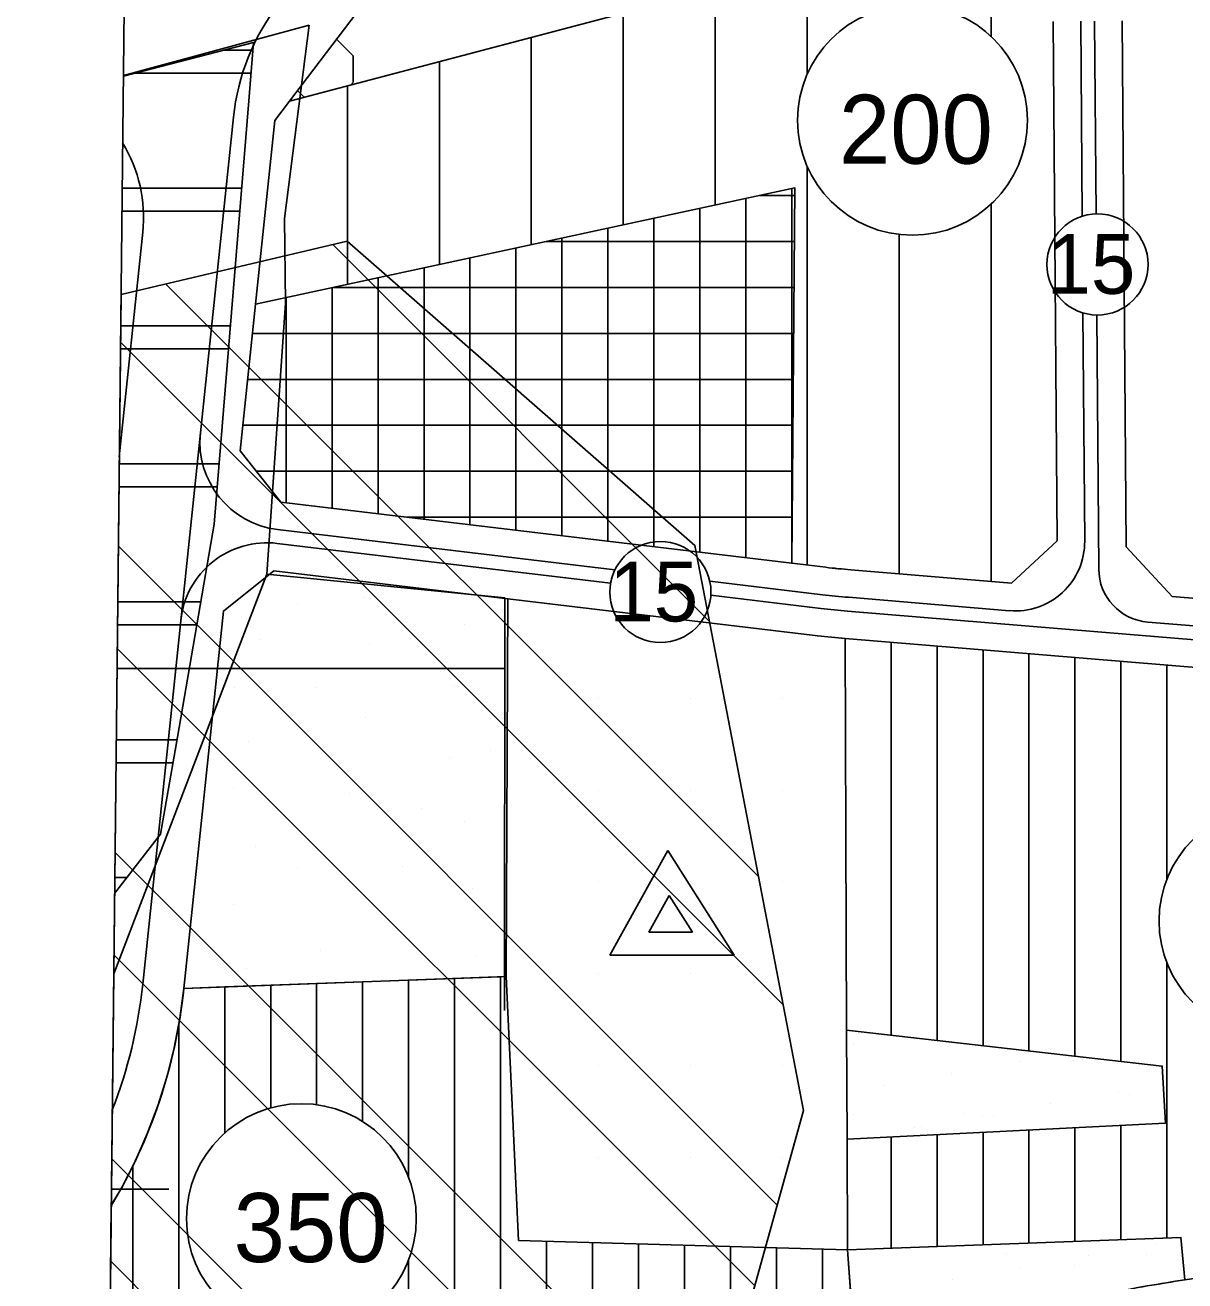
# Model space of a CAD drawing. Extents: x 419109 to 421295, y 4452223 to 4457798.
# Drawn here: x 419108.7 to 419361, y 4453980 to 4454253.2 of the extents above; entities that cross this region are included whole.
import ezdxf

# ---------------------------------------------------------------- set-up
doc = ezdxf.new("R2010")
doc.units = 0
for name, color, linetype in [('ADA', 7, 'Continuous'), ('ADAKENARI', 7, 'Continuous'), ('Default', 7, 'Continuous'), ('KALDIRIM', 7, 'Continuous'), ('KD_DAIRE', 7, 'Continuous'), ('KD_YGEN', 7, 'Continuous'), ('LJ_SEMBOL', 7, 'Continuous'), ('PAFTALAMA', 7, 'Continuous'), ('PL_AYA_AGACLANDIRIL', 7, 'Continuous'), ('PL_AYA_PARK_DINLENME', 7, 'Continuous'), ('PL_K_TALI_IS_MRK', 7, 'Continuous'), ('PL_KON_MEV_200', 7, 'Continuous'), ('PL_KON_MEV_350', 7, 'Continuous'), ('PL_SAY_ORTAOGRETIM', 7, 'Continuous'), ('rezerv yapı alan', 7, 'Continuous'), ('SIT_1_DER_DOGAL', 7, 'Continuous'), ('SIT_TR_DOGALSIT', 7, 'Continuous'), ('SM_DAIRE', 7, 'Continuous'), ('SM_TAKS', 7, 'Continuous'), ('SN_JE_SIVILASMA', 7, 'Continuous'), ('SN_TR_SIVILASMA', 7, 'Continuous'), ('TR_AGACALANI', 7, 'Continuous'), ('TR_AZYOGUNKONUT', 7, 'Continuous'), ('TR_ORTAEGITIM', 7, 'Continuous'), ('TR_ORTAYOGUNKONUT', 7, 'Continuous'), ('TR_PARKALANI', 7, 'Continuous'), ('TR_TALIISMERK', 7, 'Continuous')]:
    doc.layers.add(name, color=color, linetype=linetype)

# ---------------------------------------------------------------- blocks, each defined once
blk = doc.blocks.new('POINT_DISPLAY')
at = {"layer": 'Default'}
blk.add_line((0, 0), (0, 0), dxfattribs=at)

msp = doc.modelspace()

# ---------------------------------------------------------------- linework, layer by layer
at = {"layer": 'ADA'}
for p, q in [((419166.21, 4454236.66), (419331.42, 4454280.21)), ((419158.82, 4454192.46), (419276.17, 4454217.78)), ((419276.17, 4454217.78), (419275.48, 4454136.13)), ((419213.73, 4454128.4), (419213.38, 4454046.22)), ((419287.07, 4454119.75), (419287.4, 4454034.53)), ((419213.38, 4454046.22), (419143.26, 4454043.64)), ((419216.07, 4453988.81), (419213.38, 4454046.22)), ((419287.4, 4454034.53), (419287.49, 4454010.85)), ((419356.07, 4454026.75), (419287.4, 4454034.53)), ((419356.74, 4454014.33), (419356.07, 4454026.75)), ((419287.49, 4454010.85), (419356.74, 4454014.33)), ((419287.49, 4454010.85), (419287.58, 4453986.8)), ((419287.58, 4453986.8), (419216.07, 4453988.81)), ((419360.1, 4453989.49), (419287.58, 4453986.8)), ((419360.98, 4453980.26), (419360.1, 4453989.49)), ((419287.58, 4453986.8), (419289.1, 4453966.24))]:
    msp.add_line(p, q, dxfattribs=at)
at = {"layer": 'ADAKENARI'}
for p, q in [((419166.21, 4454236.66), (419188.8, 4454266.34)), ((419332.34, 4454253.99), (419333.19, 4454140.97)), ((419348.2, 4454139.73), (419347.34, 4454254.1)), ((419163, 4454232.45), (419166.21, 4454236.66)), ((419158.82, 4454192.46), (419163, 4454232.45)), ((419155.48, 4454160.55), (419158.82, 4454192.46)), ((419164.37, 4454149.41), (419155.48, 4454160.55)), ((419275.48, 4454136.13), (419164.37, 4454149.41)), ((419333.19, 4454140.97), (419323.3, 4454131.8)), ((419358.24, 4454128.9), (419348.2, 4454139.73)), ((419282.89, 4454135.24), (419275.48, 4454136.13)), ((419151.84, 4454125.73), (419162.81, 4454134.49)), ((419162.81, 4454134.49), (419213.73, 4454128.4)), ((419323.3, 4454131.8), (419288.31, 4454134.7)), ((419213.73, 4454128.4), (419281.11, 4454120.35)), ((419364.39, 4454128.39), (419358.24, 4454128.9)), ((419143.26, 4454043.64), (419151.84, 4454125.73)), ((419287.07, 4454119.75), (419365.19, 4454113.28))]:
    msp.add_line(p, q, dxfattribs=at)
for centre, radius, start, end in [((419300.69, 4454284.18), 150, 263.1826, 265.2652), ((419300.69, 4454284.18), 165, 263.1826, 265.2652), ((419028.88, 4454055.6), 115, 329.0052, 354.0304), ((419411.58, 4453644.04), 340, 98.5592, 101.3544)]:
    msp.add_arc(centre, radius, start, end, dxfattribs=at)
at = {"layer": 'KALDIRIM'}
for p, q in [((419338.34, 4454254.04), (419338.66, 4454211.61)), ((419341.34, 4454254.06), (419341.65, 4454212.12)), ((419154.03, 4454233.14), (419146.85, 4454164.49)), ((419134.32, 4454208.11), (419129.21, 4454159.24)), ((419338.81, 4454190.58), (419339.19, 4454140.96)), ((419341.82, 4454190.12), (419342.23, 4454134.83)), ((419146.85, 4454164.49), (419134.31, 4454044.57)), ((419163.65, 4454143.46), (419237, 4454134.69)), ((419163.54, 4454140.45), (419236.06, 4454131.78)), ((419257.64, 4454132.22), (419282.17, 4454129.29)), ((419257.87, 4454129.17), (419281.82, 4454126.31)), ((419287.82, 4454128.72), (419322.86, 4454125.81)), ((419287.57, 4454125.73), (419364.87, 4454119.32)), ((419352.91, 4454123.32), (419364.71, 4454122.35))]:
    msp.add_line(p, q, dxfattribs=at)
for centre, radius, start, end in [((419202.33, 4454228.09), 48.57, 111.3758, 174.0304), ((419103.29, 4454211.36), 31.19, 354.0304, 31.3284), ((419165.92, 4454162.5), 19.18, 174.0304, 263.1826), ((419161.3, 4454121.76), 18.82, 83.1826, 174.0304), ((419324.11, 4454140.84), 15.08, 265.2652, 0.4321), ((419353.87, 4454134.92), 11.63, 180.4321, 265.2652), ((419300.69, 4454284.18), 156, 263.1826, 265.2652), ((419300.69, 4454284.18), 159, 263.1826, 265.2652), ((419028.88, 4454055.6), 106, 338.7646, 354.0304)]:
    msp.add_arc(centre, radius, start, end, dxfattribs=at)
at = {"layer": 'KD_DAIRE'}
for centre in [(419341.97, 4454201.12), (419246.89, 4454129.87)]:
    msp.add_circle(centre, 11, dxfattribs=at)
at = {"layer": 'LJ_SEMBOL'}
for p, q in [((419248.48, 4454073.67), (419235.93, 4454050.86)), ((419262.95, 4454050.86), (419248.48, 4454073.67)), ((419248.78, 4454063.85), (419244.39, 4454055.86)), ((419253.86, 4454055.86), (419248.78, 4454063.85)), ((419244.39, 4454055.86), (419253.86, 4454055.86)), ((419235.93, 4454050.86), (419262.95, 4454050.86))]:
    msp.add_line(p, q, dxfattribs=at)
at = {"layer": 'PAFTALAMA'}
for q in [(419127.5, 4454000), (419140, 4454000)]:
    msp.add_line((419127.5, 4454000), q, dxfattribs=at)
msp.add_lwpolyline([(419138.44, 4455021.89), (419108.72, 4452245.78), (421237.47, 4452223.29), (421266.41, 4454999.4)], dxfattribs=at)
at = {"layer": 'PL_AYA_AGACLANDIRIL'}
msp.add_lwpolyline([(419335.61, 4454333.08), (419625.89, 4454484.2), (419748.88, 4454560.22), (419763.11, 4454557.27), (419777.73, 4454536.32), (419751.4, 4454522.48), (419381.25, 4454328.3), (419322.49, 4454300.11), (419331.42, 4454280.21), (419166.21, 4454236.66), (419188.8, 4454266.34), (419199.02, 4454270.36), (419218.9, 4454278.48), (419238.67, 4454286.89), (419258.31, 4454295.58), (419277.83, 4454304.55), (419297.23, 4454313.79), (419316.49, 4454323.3)], close=True, dxfattribs=at)
at = {"layer": 'PL_AYA_PARK_DINLENME'}
msp.add_lwpolyline([(419152.13, 4454043.96), (419162.13, 4454044.33), (419172.13, 4454044.7), (419182.13, 4454045.07), (419192.13, 4454045.44), (419202.13, 4454045.81), (419212.13, 4454046.18), (419213.38, 4454046.22), (419213.73, 4454128.4), (419162.81, 4454134.49), (419151.84, 4454125.73), (419143.26, 4454043.64), (419152.13, 4454043.96)], dxfattribs=at)
for points in [[(419287.4, 4454034.53), (419356.07, 4454026.75), (419356.74, 4454014.33), (419287.49, 4454010.85)], [(419344.64, 4453977.39), (419289.1, 4453966.24), (419287.58, 4453986.8), (419360.1, 4453989.49), (419360.98, 4453980.26), (419358.93, 4453979.94), (419356.88, 4453979.61), (419354.84, 4453979.27), (419352.79, 4453978.92), (419350.75, 4453978.56), (419348.71, 4453978.18), (419346.68, 4453977.79)]]:
    msp.add_lwpolyline(points, close=True, dxfattribs=at)
at = {"layer": 'PL_K_TALI_IS_MRK'}
msp.add_lwpolyline([(419275.48, 4454136.13), (419164.37, 4454149.41), (419155.48, 4454160.55), (419158.82, 4454192.46), (419276.17, 4454217.78)], close=True, dxfattribs=at)
at = {"layer": 'PL_KON_MEV_200'}
for points in [[(419398.44, 4454287.72), (419397.53, 4454245.4), (419458.16, 4454246.67), (419459.55, 4454147.55), (419449.56, 4454144.69), (419364.39, 4454128.39), (419358.24, 4454128.9), (419348.2, 4454139.73), (419347.34, 4454254.1)], [(419332.34, 4454253.99), (419333.19, 4454140.97), (419323.3, 4454131.8), (419288.31, 4454134.7), (419287.63, 4454134.75), (419286.95, 4454134.81), (419286.27, 4454134.88), (419285.6, 4454134.94), (419284.92, 4454135.02), (419284.24, 4454135.09), (419283.56, 4454135.16), (419282.89, 4454135.24), (419275.48, 4454136.13), (419276.17, 4454217.78), (419158.82, 4454192.46), (419163, 4454232.45), (419166.21, 4454236.66), (419331.42, 4454280.21)]]:
    msp.add_lwpolyline(points, dxfattribs=at)
at = {"layer": 'PL_KON_MEV_350'}
msp.add_line((419127.46, 4453996.46), (419126.98, 4453951.4), dxfattribs=at)
msp.add_lwpolyline([(419365.19, 4454113.28), (419454.7, 4454130.4), (419465.54, 4454122.33), (419477.75, 4454003.77), (419468.84, 4453992.7), (419373.33, 4453981.88), (419371.78, 4453981.71), (419370.23, 4453981.52), (419368.69, 4453981.33), (419367.14, 4453981.13), (419365.6, 4453980.92), (419364.06, 4453980.71), (419362.52, 4453980.48), (419360.98, 4453980.26), (419360.1, 4453989.49), (419287.58, 4453986.8), (419287.49, 4454010.85), (419356.74, 4454014.33), (419356.07, 4454026.75), (419287.4, 4454034.53), (419287.07, 4454119.75)], close=True, dxfattribs=at)
msp.add_lwpolyline([(419126.98, 4453951.4), (419176.13, 4453950.58), (419184.18, 4453950.55), (419192.23, 4453950.74), (419200.27, 4453951.15), (419208.3, 4453951.77), (419216.31, 4453952.61), (419224.3, 4453953.66), (419232.25, 4453954.93), (419240.17, 4453956.41), (419289.1, 4453966.24), (419287.58, 4453986.8), (419216.07, 4453988.81), (419213.38, 4454046.22), (419143.26, 4454043.64), (419142.39, 4454037.15), (419141.16, 4454030.72), (419139.56, 4454024.37), (419137.61, 4454018.12), (419135.3, 4454012), (419132.64, 4454006.01), (419129.66, 4454000.19), (419127.46, 4453996.46)], dxfattribs=at)
at = {"layer": 'PL_SAY_ORTAOGRETIM'}
msp.add_lwpolyline([(419216.07, 4453988.81), (419213.38, 4454046.22), (419213.73, 4454128.4), (419281.11, 4454120.35), (419281.85, 4454120.26), (419282.6, 4454120.18), (419283.34, 4454120.1), (419284.09, 4454120.02), (419284.83, 4454119.95), (419285.58, 4454119.88), (419286.33, 4454119.81), (419287.07, 4454119.75), (419287.4, 4454034.53), (419287.49, 4454010.85), (419287.58, 4453986.8)], close=True, dxfattribs=at)
at = {"layer": 'rezerv yapı alan'}
for p, q in [((419130.09, 4454242.23), (419170.49, 4454253.17)), ((419170.49, 4454253.17), (419165.15, 4454211.09)), ((419165.15, 4454211.09), (419165.36, 4454192.7)), ((419165.36, 4454192.7), (419161.28, 4454133.77)), ((419161.28, 4454133.77), (419213.05, 4454128.59)), ((419213.05, 4454128.59), (419212.97, 4454038.83)), ((419128.71, 4454113.24), (419213.04, 4454113.24))]:
    msp.add_line(p, q, dxfattribs=at)
msp.add_lwpolyline([(419128, 4454046.79), (419161.28, 4454133.77)], dxfattribs=at)
at = {"layer": 'SIT_1_DER_DOGAL'}
msp.add_lwpolyline([(419130.09, 4454242.09), (419158.39, 4454249.41), (419157.35, 4454236.69), (419149.83, 4454144.61), (419141.83, 4454098.27), (419138.19, 4454077.17), (419128.19, 4454064.31)], dxfattribs=at)
at = {"layer": 'SIT_TR_DOGALSIT'}
for p, q in [((419151.92, 4454247.74), (419158.26, 4454247.74)), ((419132.6, 4454242.74), (419157.85, 4454242.74)), ((419129.83, 4454217.74), (419155.8, 4454217.74)), ((419129.78, 4454212.74), (419155.39, 4454212.74)), ((419129.51, 4454187.74), (419153.35, 4454187.74)), ((419129.46, 4454182.74), (419152.94, 4454182.74)), ((419129.19, 4454157.74), (419150.9, 4454157.74)), ((419129.14, 4454152.74), (419150.49, 4454152.74)), ((419128.87, 4454127.74), (419146.92, 4454127.74)), ((419128.81, 4454122.74), (419146.05, 4454122.74)), ((419128.55, 4454097.74), (419141.74, 4454097.74)), ((419128.49, 4454092.74), (419140.88, 4454092.74)), ((419128.23, 4454067.74), (419130.85, 4454067.74))]:
    msp.add_line(p, q, dxfattribs=at)
at = {"layer": 'SM_DAIRE'}
for centre in [(419301.73, 4454232.48), (419380.36, 4454058.32), (419168.81, 4453993.56)]:
    msp.add_circle(centre, 25, dxfattribs=at)
at = {"layer": 'SN_JE_SIVILASMA'}
msp.add_line((419129.58, 4454194.61), (419124.55, 4453724.28), dxfattribs=at)
msp.add_lwpolyline([(419124.55, 4453724.28), (419178.79, 4453832.76), (419254.42, 4453932.02), (419278.05, 4454017.11), (419254.42, 4454140.01), (419178.79, 4454206.19), (419129.58, 4454194.61)], dxfattribs=at)
at = {"layer": 'SN_TR_SIVILASMA'}
for p, q in [((419257.6, 4454123.47), (419175.62, 4454205.44)), ((419268.29, 4454067.88), (419139.27, 4454196.89)), ((419273.63, 4454040.08), (419129.47, 4454184.24)), ((419272.32, 4453996.49), (419129, 4454139.82)), ((419267.44, 4453978.92), (419128.76, 4454117.6)), ((419257.68, 4453943.78), (419128.28, 4454073.18)), ((419251.2, 4453927.81), (419128.05, 4454050.96)), ((419231.79, 4453902.32), (419127.57, 4454006.54)), ((419222.08, 4453889.58), (419127.33, 4453984.33))]:
    msp.add_line(p, q, dxfattribs=at)
at = {"layer": 'TR_AGACALANI'}
for p, q in [((419180.07, 4454246.47), (419176.44, 4454250.1)), ((419180.07, 4454240.74), (419180.07, 4454246.48)), ((419179.54, 4454240.17), (419180.08, 4454240.72)), ((419169.43, 4454237.51), (419167.97, 4454238.97))]:
    msp.add_line(p, q, dxfattribs=at)
at = {"layer": 'TR_AZYOGUNKONUT'}
for p, q in [((419318.82, 4454250.73), (419318.82, 4454276.89)), ((419278.82, 4454242.48), (419278.82, 4454266.34)), ((419258.82, 4454214.04), (419258.82, 4454261.07)), ((419238.82, 4454209.73), (419238.82, 4454255.8)), ((419218.82, 4454205.41), (419218.82, 4454250.53)), ((419198.82, 4454201.09), (419198.82, 4454245.26)), ((419178.82, 4454196.78), (419178.82, 4454239.98)), ((419278.82, 4454135.73), (419278.82, 4454222.48)), ((419318.82, 4454132.17), (419318.82, 4454214.23)), ((419298.82, 4454133.82), (419298.82, 4454207.65))]:
    msp.add_line(p, q, dxfattribs=at)
at = {"layer": 'TR_ORTAYOGUNKONUT'}
for p, q in [((419297.07, 4454033.44), (419297.07, 4454118.92)), ((419307.07, 4454032.3), (419307.07, 4454118.09)), ((419317.07, 4454031.17), (419317.07, 4454117.26)), ((419327.07, 4454030.04), (419327.07, 4454116.43)), ((419337.07, 4454028.9), (419337.07, 4454115.61)), ((419347.07, 4454027.77), (419347.07, 4454114.78)), ((419357.07, 4454067.43), (419357.07, 4454113.95)), ((419357.07, 4453989.37), (419357.07, 4454049.21)), ((419202.13, 4453951.3), (419202.13, 4454045.81)), ((419212.13, 4453952.17), (419212.13, 4454046.18)), ((419152.13, 4454012.18), (419152.13, 4454043.96)), ((419162.13, 4454017.65), (419162.13, 4454044.33)), ((419172.13, 4454018.34), (419172.13, 4454044.7)), ((419182.13, 4454014.72), (419182.13, 4454045.07)), ((419192.13, 4454002.58), (419192.13, 4454045.44)), ((419142.13, 4453951.14), (419142.13, 4454035.78)), ((419327.07, 4453988.26), (419327.07, 4454012.84)), ((419337.07, 4453988.63), (419337.07, 4454013.34)), ((419347.07, 4453989), (419347.07, 4454013.84)), ((419297.07, 4453987.15), (419297.07, 4454011.33)), ((419307.07, 4453987.52), (419307.07, 4454011.83)), ((419317.07, 4453987.89), (419317.07, 4454012.34)), ((419132.13, 4453951.31), (419132.13, 4454005.01)), ((419222.13, 4453953.38), (419222.13, 4453988.64)), ((419232.13, 4453954.91), (419232.13, 4453988.36)), ((419242.13, 4453956.8), (419242.13, 4453988.08)), ((419252.13, 4453958.81), (419252.13, 4453987.8)), ((419262.13, 4453960.82), (419262.13, 4453987.52)), ((419272.13, 4453962.83), (419272.13, 4453987.24)), ((419282.13, 4453964.84), (419282.13, 4453986.95)), ((419192.13, 4453950.74), (419192.13, 4453984.55))]:
    msp.add_line(p, q, dxfattribs=at)
at = {"layer": 'TR_TALIISMERK'}
for p, q in [((419275.48, 4454136.13), (419275.48, 4454217.64)), ((419265.48, 4454137.32), (419265.48, 4454215.48)), ((419268.49, 4454216.13), (419276.15, 4454216.13)), ((419255.48, 4454138.52), (419255.48, 4454213.32)), ((419245.48, 4454139.72), (419245.48, 4454211.16)), ((419225.48, 4454142.11), (419225.48, 4454206.85)), ((419235.48, 4454140.91), (419235.48, 4454209.01)), ((419215.48, 4454143.3), (419215.48, 4454204.69)), ((419222.16, 4454206.13), (419276.07, 4454206.13)), ((419205.48, 4454144.5), (419205.48, 4454202.53)), ((419195.48, 4454145.69), (419195.48, 4454200.37)), ((419175.48, 4454148.08), (419175.48, 4454196.06)), ((419175.82, 4454196.13), (419275.98, 4454196.13)), ((419185.48, 4454146.89), (419185.48, 4454198.21)), ((419165.48, 4454149.28), (419165.48, 4454193.9)), ((419158.16, 4454186.13), (419275.9, 4454186.13)), ((419157.11, 4454176.13), (419275.82, 4454176.13)), ((419156.07, 4454166.13), (419275.73, 4454166.13)), ((419159.01, 4454156.13), (419275.65, 4454156.13)), ((419191.84, 4454146.13), (419275.57, 4454146.13))]:
    msp.add_line(p, q, dxfattribs=at)

# ---------------------------------------------------------------- block references
at = {"layer": 'TR_ORTAEGITIM', "xscale": 0.1, "yscale": 0.10000000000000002}
for p in [(419233.38, 4454106.8), (419253.38, 4454106.8), (419273.38, 4454106.8), (419233.38, 4454086.8), (419253.38, 4454086.8), (419273.38, 4454086.8), (419233.38, 4454066.8), (419253.38, 4454066.8), (419273.38, 4454066.8), (419233.38, 4454046.8), (419253.38, 4454046.8), (419273.38, 4454046.8), (419233.38, 4454026.8), (419253.38, 4454026.8), (419273.38, 4454026.8), (419233.38, 4454006.8), (419253.38, 4454006.8), (419273.38, 4454006.8)]:
    msp.add_blockref('POINT_DISPLAY', p, dxfattribs=at)
at = {"layer": 'TR_PARKALANI', "xscale": 0.1, "yscale": 0.10000000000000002}
for p in [(419182.41, 4454128.67), (419167.89, 4454127.38), (419204.35, 4454122.87), (419159.82, 4454119.64), (419183.7, 4454118.35), (419154.34, 4454108.99), (419172.09, 4454108.99), (419202.09, 4454109.64), (419182.73, 4454102.54), (419157.24, 4454097.38), (419209.84, 4454095.44), (419201.12, 4454093.83), (419154.02, 4454087.05), (419179.25, 4454086.13), (419194.99, 4454082.86), (419204.35, 4454079.95), (419158.86, 4454074.47), (419190.8, 4454070.27), (419167.89, 4454069.95), (419205.96, 4454065.43), (419154.02, 4454061.88), (419192.41, 4454054.46), (419173.05, 4454051.88), (419206.93, 4454050.59), (419156.92, 4454048.01), (419288.85, 4454031.41), (419325.05, 4454027.64), (419336.71, 4454028.04), (419310.28, 4454025.04), (419295.51, 4454022.43), (419346.49, 4454021.27), (419331.71, 4454018.66), (419348.89, 4454020.49), (419288.93, 4454016.15), (419313.05, 4454016.53), (419316.94, 4454016.06), (419319.34, 4454015.87), (419302.17, 4454013.45), (419303.7, 4454013.55), (419354.78, 4453988.24), (419289.03, 4453986.8), (419322.12, 4453986.03), (419340.01, 4453985.64), (419352.54, 4453985.74), (419325.24, 4453983.03), (419336.9, 4453983.42), (419310.46, 4453980.43)]:
    msp.add_blockref('POINT_DISPLAY', p, dxfattribs=at)

# ---------------------------------------------------------------- texts
at = {"layer": 'KD_YGEN'}
for p in [(419330.87, 4454194.73), (419235.79, 4454123.47)]:
    msp.add_text('15', height=13, dxfattribs=at).set_placement(p)
at = {"layer": 'SM_TAKS'}
for s, p in [('200', (419285.74, 4454223.03)), ('350', (419154.07, 4453984.12))]:
    msp.add_text(s, height=15, dxfattribs=at).set_placement(p)

doc.saveas('drawing.dxf')
